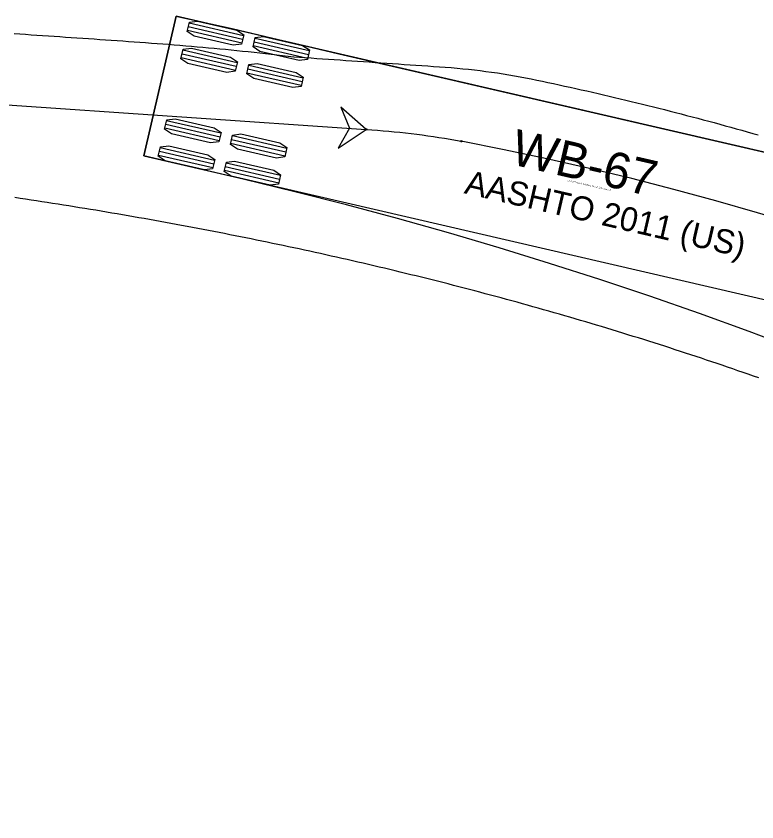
# Model space of a CAD drawing. Extents: x 2175591 to 2194071, y 76570 to 86955.
# Drawn here: x 2192756.76 to 2192800.61, y 86899.14 to 86946.86 of the extents above; entities that cross this region are included whole.
import ezdxf

# ---------------------------------------------------------------- set-up
doc = ezdxf.new("R2010")
doc.units = 0
doc.layers.add('-NOPLT', color=7, linetype='Continuous')
doc.layers.add('C-UTIL-STRM-TEXT', color=7, linetype='Continuous')

msp = doc.modelspace()

# ---------------------------------------------------------------- linework, layer by layer
at = {"layer": '-NOPLT'}
msp.add_line((2192696.007, 86945.713), (2192777.484, 86940.151), dxfattribs=at)
for points in [[(2192756.64, 86945.834), (2192756.978, 86945.811), (2192757.317, 86945.788), (2192757.655, 86945.765), (2192757.993, 86945.742), (2192758.331, 86945.719), (2192758.67, 86945.696), (2192759.008, 86945.672), (2192759.347, 86945.649), (2192759.685, 86945.626), (2192760.024, 86945.603), (2192760.362, 86945.58), (2192760.701, 86945.557), (2192761.04, 86945.534), (2192761.378, 86945.511), (2192761.717, 86945.487), (2192762.056, 86945.464), (2192762.395, 86945.441), (2192762.734, 86945.418), (2192763.073, 86945.394), (2192763.412, 86945.37), (2192763.751, 86945.346), (2192764.09, 86945.322), (2192764.429, 86945.297), (2192764.767, 86945.272), (2192765.106, 86945.247), (2192765.445, 86945.221), (2192765.783, 86945.195), (2192766.122, 86945.168), (2192766.46, 86945.14), (2192766.798, 86945.112), (2192767.136, 86945.084), (2192767.474, 86945.054), (2192767.811, 86945.024), (2192768.148, 86944.994), (2192768.486, 86944.963), (2192768.823, 86944.931), (2192769.16, 86944.899), (2192769.496, 86944.865), (2192769.833, 86944.832), (2192770.169, 86944.797), (2192770.506, 86944.762), (2192770.842, 86944.727), (2192771.178, 86944.69), (2192771.513, 86944.654), (2192771.849, 86944.616), (2192772.185, 86944.578), (2192772.52, 86944.539), (2192772.855, 86944.5), (2192773.19, 86944.46), (2192773.53, 86944.43), (2192773.873, 86944.407), (2192774.217, 86944.384), (2192774.56, 86944.36), (2192774.903, 86944.337), (2192775.247, 86944.313), (2192775.591, 86944.29), (2192775.935, 86944.266), (2192776.279, 86944.243), (2192776.624, 86944.219), (2192776.969, 86944.196), (2192777.313, 86944.172), (2192777.659, 86944.149), (2192778.004, 86944.125), (2192778.349, 86944.102), (2192778.695, 86944.078), (2192779.041, 86944.054), (2192779.387, 86944.031), (2192779.734, 86944.007), (2192780.08, 86943.983), (2192780.427, 86943.96), (2192780.774, 86943.936), (2192781.121, 86943.912), (2192781.469, 86943.889), (2192781.817, 86943.865)], [(2192781.817, 86943.865), (2192782.164, 86943.84), (2192782.511, 86943.813), (2192782.857, 86943.783), (2192783.201, 86943.751), (2192783.545, 86943.716), (2192783.887, 86943.678), (2192784.229, 86943.637), (2192784.569, 86943.594), (2192784.908, 86943.548), (2192785.246, 86943.499), (2192785.583, 86943.447), (2192785.919, 86943.393), (2192786.254, 86943.336), (2192786.587, 86943.276), (2192786.92, 86943.213), (2192787.251, 86943.147), (2192787.581, 86943.079), (2192787.911, 86943.01), (2192788.241, 86942.939), (2192788.57, 86942.868), (2192788.9, 86942.797), (2192789.229, 86942.725), (2192789.558, 86942.652), (2192789.887, 86942.579), (2192790.216, 86942.505), (2192790.545, 86942.43), (2192790.874, 86942.355), (2192791.203, 86942.28), (2192791.532, 86942.203), (2192791.86, 86942.126), (2192792.189, 86942.049), (2192792.517, 86941.971), (2192792.845, 86941.892), (2192793.174, 86941.813), (2192793.502, 86941.733), (2192793.83, 86941.653), (2192794.157, 86941.572), (2192794.485, 86941.49), (2192794.813, 86941.408), (2192795.14, 86941.325), (2192795.467, 86941.242), (2192795.794, 86941.158), (2192796.121, 86941.073), (2192796.448, 86940.988), (2192796.775, 86940.903), (2192797.102, 86940.816), (2192797.428, 86940.729), (2192797.754, 86940.642), (2192798.081, 86940.554), (2192798.406, 86940.465), (2192798.732, 86940.376), (2192799.058, 86940.286), (2192799.384, 86940.196), (2192799.709, 86940.105), (2192800.034, 86940.013), (2192800.359, 86939.921), (2192800.684, 86939.829)], [(2192777.484, 86940.151), (2192775.984, 86941.474), (2192776.486, 86940.219), (2192775.818, 86939.045), (2192777.484, 86940.151)], [(2192777.484, 86940.151), (2192777.817, 86940.129), (2192778.149, 86940.104), (2192778.481, 86940.077), (2192778.813, 86940.048), (2192779.145, 86940.016), (2192779.477, 86939.983), (2192779.808, 86939.947), (2192780.139, 86939.909), (2192780.47, 86939.869), (2192780.801, 86939.826), (2192781.131, 86939.78), (2192781.461, 86939.733), (2192781.791, 86939.683), (2192782.12, 86939.63), (2192782.449, 86939.575), (2192782.777, 86939.517), (2192783.105, 86939.457)], [(2192800.714, 86925.434), (2192800.407, 86925.542), (2192800.099, 86925.65), (2192799.791, 86925.757), (2192799.482, 86925.864), (2192799.174, 86925.97), (2192798.865, 86926.076), (2192798.557, 86926.182), (2192798.248, 86926.287), (2192797.939, 86926.391), (2192797.629, 86926.495), (2192797.32, 86926.598), (2192797.011, 86926.701), (2192796.701, 86926.804), (2192796.391, 86926.906), (2192796.081, 86927.007), (2192795.771, 86927.108), (2192795.461, 86927.209), (2192795.151, 86927.309), (2192794.84, 86927.408), (2192794.53, 86927.508), (2192794.219, 86927.606), (2192793.908, 86927.704), (2192793.597, 86927.802), (2192793.286, 86927.899), (2192792.975, 86927.996), (2192792.663, 86928.092), (2192792.352, 86928.188), (2192792.04, 86928.283), (2192791.728, 86928.378), (2192791.417, 86928.472), (2192791.105, 86928.566), (2192790.792, 86928.659), (2192790.48, 86928.752), (2192790.168, 86928.844), (2192789.855, 86928.936), (2192789.543, 86929.028), (2192789.23, 86929.119), (2192788.918, 86929.209), (2192788.605, 86929.299), (2192788.292, 86929.389), (2192787.979, 86929.478), (2192787.666, 86929.566), (2192787.352, 86929.654), (2192787.039, 86929.742), (2192786.726, 86929.829), (2192786.412, 86929.916), (2192786.099, 86930.002), (2192785.785, 86930.088), (2192785.472, 86930.173), (2192785.158, 86930.258), (2192784.844, 86930.342), (2192784.53, 86930.426), (2192784.216, 86930.509), (2192783.903, 86930.592), (2192783.589, 86930.674), (2192783.274, 86930.756), (2192782.96, 86930.838), (2192782.646, 86930.919), (2192782.332, 86931), (2192782.018, 86931.08), (2192781.704, 86931.159), (2192781.389, 86931.238), (2192781.075, 86931.317), (2192780.76, 86931.395), (2192780.446, 86931.473), (2192780.131, 86931.551), (2192779.817, 86931.627), (2192779.502, 86931.704), (2192779.188, 86931.78), (2192778.873, 86931.855), (2192778.558, 86931.931), (2192778.244, 86932.005), (2192777.929, 86932.079), (2192777.614, 86932.153), (2192777.299, 86932.226), (2192776.984, 86932.299), (2192776.669, 86932.372), (2192776.354, 86932.444), (2192776.039, 86932.515), (2192775.724, 86932.586), (2192775.409, 86932.657), (2192775.094, 86932.727), (2192774.778, 86932.797), (2192774.463, 86932.866), (2192774.148, 86932.935), (2192773.832, 86933.004), (2192773.517, 86933.072), (2192773.201, 86933.14), (2192772.886, 86933.207), (2192772.57, 86933.274), (2192772.254, 86933.34), (2192771.938, 86933.406), (2192771.623, 86933.472), (2192771.307, 86933.537), (2192770.991, 86933.602), (2192770.675, 86933.666), (2192770.359, 86933.73), (2192770.042, 86933.794), (2192769.726, 86933.857), (2192769.41, 86933.92), (2192769.093, 86933.982), (2192768.777, 86934.044), (2192768.46, 86934.105), (2192768.144, 86934.167), (2192767.827, 86934.227), (2192767.51, 86934.288), (2192767.193, 86934.348), (2192766.876, 86934.407), (2192766.559, 86934.466), (2192766.242, 86934.525), (2192765.925, 86934.584), (2192765.608, 86934.642), (2192765.29, 86934.699), (2192764.973, 86934.757), (2192764.655, 86934.813), (2192764.338, 86934.87), (2192764.02, 86934.926), (2192763.702, 86934.982), (2192763.384, 86935.037), (2192763.066, 86935.092), (2192762.748, 86935.147), (2192762.43, 86935.201), (2192762.112, 86935.255), (2192761.793, 86935.309), (2192761.475, 86935.362), (2192761.156, 86935.415), (2192760.837, 86935.467), (2192760.518, 86935.519), (2192760.199, 86935.571), (2192759.88, 86935.622), (2192759.561, 86935.673), (2192759.242, 86935.724), (2192758.923, 86935.774), (2192758.603, 86935.824), (2192758.283, 86935.874), (2192757.964, 86935.923), (2192757.644, 86935.972), (2192757.324, 86936.021), (2192757.004, 86936.069), (2192756.683, 86936.117)]]:
    msp.add_lwpolyline(points, dxfattribs=at)
msp.add_lwpolyline([(2192777.484, 86940.151), (2192775.984, 86941.474), (2192776.486, 86940.219), (2192775.818, 86939.045)], close=True, dxfattribs=at)
for centre in [(2192777.484, 86940.151), (2192777.484, 86940.151), (2192783.105, 86939.457), (2192783.105, 86939.457)]:
    msp.add_circle(centre, 0.0417, dxfattribs=at)
msp.add_arc((2192748.446, 86757.375), 185.351, 28.75355, 79.22293, dxfattribs=at)
at = {"layer": 'C-UTIL-STRM-TEXT'}
for p, q in [((2192766.227, 86946.865), (2192764.311, 86938.583)), ((2192817.863, 86934.919), (2192766.227, 86946.865)), ((2192770.219, 86945.706), (2192767.004, 86946.45)), ((2192770.115, 86945.259), (2192766.9, 86946.003)), ((2192770.167, 86945.483), (2192766.952, 86946.227)), ((2192774.064, 86944.581), (2192770.849, 86945.325)), ((2192774.116, 86944.804), (2192770.901, 86945.548)), ((2192769.847, 86944.098), (2192766.632, 86944.842)), ((2192774.013, 86944.358), (2192770.797, 86945.102)), ((2192769.744, 86943.652), (2192766.529, 86944.396)), ((2192769.795, 86943.875), (2192766.58, 86944.619)), ((2192773.744, 86943.197), (2192770.529, 86943.941)), ((2192773.641, 86942.75), (2192770.426, 86943.494)), ((2192773.692, 86942.974), (2192770.477, 86943.717)), ((2192768.881, 86939.925), (2192765.666, 86940.669)), ((2192768.778, 86939.479), (2192765.563, 86940.223)), ((2192768.83, 86939.702), (2192765.615, 86940.446)), ((2192772.779, 86939.024), (2192769.563, 86939.768)), ((2192772.675, 86938.577), (2192769.46, 86939.321)), ((2192772.727, 86938.8), (2192769.512, 86939.544)), ((2192768.406, 86937.871), (2192765.191, 86938.615)), ((2192768.458, 86938.095), (2192765.243, 86938.838)), ((2192768.51, 86938.318), (2192765.294, 86939.062)), ((2192764.311, 86938.583), (2192815.948, 86926.637)), ((2192772.407, 86937.416), (2192769.192, 86938.16)), ((2192772.303, 86936.97), (2192769.088, 86937.713)), ((2192772.355, 86937.193), (2192769.14, 86937.937))]:
    msp.add_line(p, q, dxfattribs=at)
for points in [[(2192803.072, 86927.073), (2192800.153, 86928.176), (2192797.22, 86929.243), (2192794.272, 86930.272), (2192791.31, 86931.265), (2192788.335, 86932.221), (2192785.347, 86933.141), (2192782.347, 86934.025), (2192779.336, 86934.873), (2192776.311, 86935.686), (2192773.265, 86936.467), (2192770.194, 86937.217), (2192764.311, 86938.583), (2192766.227, 86946.865), (2192766.399, 86946.828), (2192766.399, 86946.828)], [(2192766.399, 86946.828), (2192769.556, 86946.127), (2192775.857, 86944.637), (2192817.863, 86934.919), (2192820.71, 86933.7), (2192823.724, 86932.373), (2192826.672, 86931.024), (2192829.654, 86929.607), (2192834.093, 86927.408), (2192838.046, 86925.753)]]:
    msp.add_lwpolyline(points, dxfattribs=at)
for points in [[(2192770.232, 86945.761), (2192770.103, 86945.204), (2192769.614, 86945.14), (2192767.299, 86945.676), (2192766.888, 86945.948), (2192767.017, 86946.505), (2192767.505, 86946.569), (2192769.82, 86946.033)], [(2192774.129, 86944.86), (2192774, 86944.302), (2192773.511, 86944.239), (2192771.196, 86944.774), (2192770.785, 86945.046), (2192770.914, 86945.604), (2192771.403, 86945.667), (2192773.717, 86945.132)], [(2192769.86, 86944.154), (2192769.731, 86943.597), (2192769.242, 86943.533), (2192766.927, 86944.068), (2192766.516, 86944.34), (2192766.645, 86944.898), (2192767.134, 86944.961), (2192769.448, 86944.426)], [(2192773.757, 86943.252), (2192773.628, 86942.695), (2192773.139, 86942.631), (2192770.824, 86943.167), (2192770.413, 86943.439), (2192770.542, 86943.996), (2192771.031, 86944.06), (2192773.346, 86943.524)], [(2192768.894, 86939.981), (2192768.765, 86939.423), (2192768.276, 86939.36), (2192765.962, 86939.895), (2192765.55, 86940.167), (2192765.679, 86940.725), (2192766.168, 86940.788), (2192768.483, 86940.253)], [(2192772.791, 86939.079), (2192772.662, 86938.522), (2192772.173, 86938.458), (2192769.859, 86938.994), (2192769.447, 86939.266), (2192769.576, 86939.823), (2192770.065, 86939.887), (2192772.38, 86939.351)], [(2192768.522, 86938.373), (2192768.393, 86937.816), (2192767.904, 86937.752), (2192765.59, 86938.288), (2192765.178, 86938.56), (2192765.307, 86939.117), (2192765.796, 86939.181), (2192768.111, 86938.645)], [(2192772.419, 86937.472), (2192772.291, 86936.914), (2192771.802, 86936.851), (2192769.487, 86937.386), (2192769.075, 86937.658), (2192769.204, 86938.215), (2192769.693, 86938.279), (2192772.008, 86937.744)]]:
    msp.add_lwpolyline(points, close=True, dxfattribs=at)

# ---------------------------------------------------------------- texts
for s, height, p in [('WB-67', 2.125, (2192785.95, 86938.114)), ('AASHTO 2011 (US)', 1.41667, (2192783.237, 86936.379)), ('(c) 2019 Transoft Solutions, Inc. All rights reserved.', 0.085, (2192789.39, 86937.1))]:
    msp.add_text(s, height=height, rotation=346.9739, dxfattribs=at).set_placement(p)

doc.saveas('drawing.dxf')
